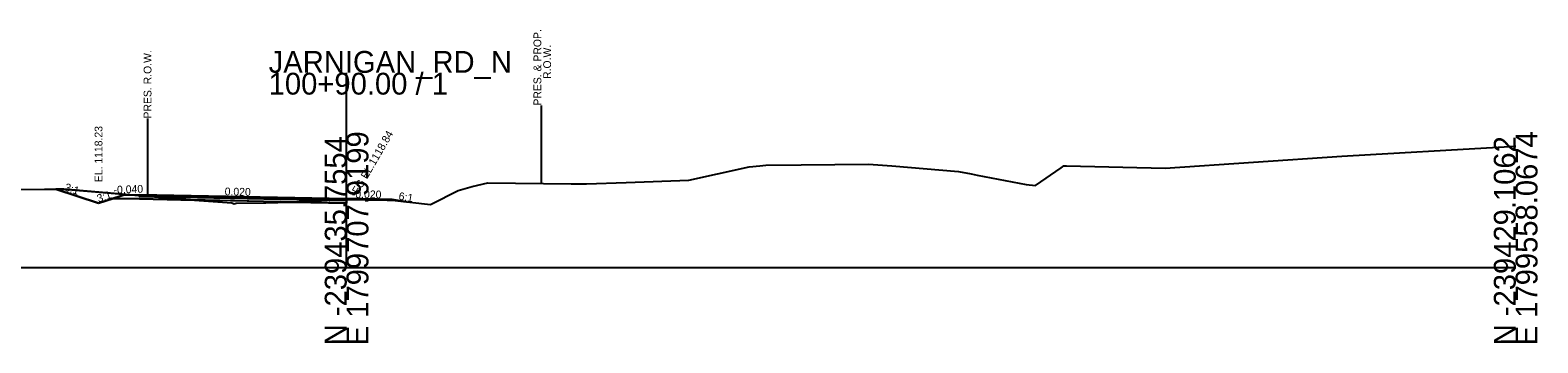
# Model space of a CAD drawing. Extents: x 214513 to 217151, y 214739 to 216780.
# Drawn here: x 214857.8 to 215051.2, y 216738.7 to 216778.8 of the extents above; entities that cross this region are included whole.
import ezdxf

# ---------------------------------------------------------------- set-up
doc = ezdxf.new("R2010")
doc.units = 0
for name, color, linetype in [('CONCEPT - TRANSPORTATION - Roads Text', 7, 'Continuous'), ('DESIGN - CENTERLINE - Proposed', 7, 'Continuous'), ('DESIGN - CENTERLINE - Proposed Text', 7, 'Continuous'), ('DESIGN - DRAINAGE - Special Ditches', 7, 'Continuous'), ('DESIGN - EARTHWORK - Shapes', 7, 'Continuous'), ('DESIGN - TRANSPORTATION - Text', 7, 'Continuous'), ('DESIGN - TYPICAL - Slope Tie Text', 7, 'Continuous'), ('SURVEY - DTM GRAPHICS - Triangles', 7, 'Continuous'), ('SURVEY - PROPERTY - ROW Lines', 7, 'Continuous'), ('XSCell', 7, 'Continuous')]:
    doc.layers.add(name, color=color, linetype=linetype)

msp = doc.modelspace()

# ---------------------------------------------------------------- linework, layer by layer
at = {"layer": 'DESIGN - DRAINAGE - Special Ditches'}
for points in [[(214866.53, 216756.6), (214861.04, 216758.43)], [(214869.7, 216757.65), (214866.53, 216756.6)], [(214871.78, 216757.74), (214871.78, 216757.49), (214877.07, 216757.38), (214898.36, 216756.95), (214898.36, 216756.62), (214877.07, 216757.05), (214871.78, 216757.16), (214868.41, 216757.22), (214869.7, 216757.65), (214871.78, 216757.74)], [(214871.78, 216757.74), (214898.36, 216757.2), (214898.36, 216757.1), (214898.36, 216757.1), (214871.78, 216757.64), (214871.78, 216757.64), (214871.78, 216757.64), (214871.78, 216757.74), (214871.78, 216757.74)], [(214871.78, 216757.64), (214898.36, 216757.1), (214898.36, 216756.95), (214898.36, 216756.95), (214871.78, 216757.49), (214871.78, 216757.49), (214871.78, 216757.49), (214871.78, 216757.64), (214871.78, 216757.64)], [(214904.19, 216757.09), (214898.36, 216757.2), (214898.36, 216757.1), (214898.36, 216757.1), (214904.19, 216756.99), (214904.19, 216756.99), (214904.19, 216756.99), (214904.19, 216757.09), (214904.19, 216757.09)], [(214904.19, 216757.09), (214906.05, 216756.78)]]:
    msp.add_lwpolyline(points, dxfattribs=at)
at = {"layer": 'DESIGN - EARTHWORK - Shapes'}
for p, q in [((214861.04, 216758.43), (214866.53, 216756.6)), ((214869.7, 216757.65), (214868.41, 216757.22)), ((214869.7, 216757.65), (214870.53, 216757.69)), ((214870.53, 216757.69), (214869.7, 216757.65)), ((214871.78, 216757.58), (214870.53, 216757.69)), ((214871.78, 216757.58), (214871.78, 216757.49)), ((214871.78, 216757.49), (214873.22, 216757.46)), ((214891.44, 216756.76), (214878.32, 216757.03)), ((214891.44, 216756.76), (214898.36, 216756.62)), ((214898.36, 216756.95), (214896.14, 216757)), ((214896.14, 216757), (214898.36, 216756.95)), ((214898.36, 216757.13), (214898.12, 216757.11)), ((214898.12, 216757.11), (214898.36, 216757.1)), ((214898.36, 216757.1), (214898.36, 216757.13)), ((214898.36, 216757.13), (214898.36, 216757.1)), ((214898.36, 216757.1), (214903.57, 216757)), ((214898.36, 216756.62), (214898.36, 216756.95)), ((214906.05, 216756.78), (214904.19, 216757.09))]:
    msp.add_line(p, q, dxfattribs=at)
for points in [[(214870.53, 216757.69), (214862.09, 216758.4), (214861.1, 216758.43), (214861.04, 216758.43)], [(214866.53, 216756.6), (214868.41, 216757.22), (214869.7, 216757.65)], [(214868.41, 216757.22), (214871.78, 216757.16), (214877.07, 216757.05), (214878.32, 216757.03)], [(214873.22, 216757.46), (214871.78, 216757.49), (214871.78, 216757.58)], [(214873.22, 216757.46), (214872.82, 216757.49), (214871.78, 216757.58)], [(214878.32, 216757.03), (214878.26, 216757.03), (214873.22, 216757.46)], [(214878.32, 216757.03), (214883.63, 216756.66), (214883.94, 216756.54), (214884.19, 216756.6), (214888.01, 216756.64), (214889.53, 216756.71), (214891.44, 216756.76)], [(214896.14, 216757), (214892.27, 216756.79), (214891.44, 216756.76)], [(214898.12, 216757.11), (214898.05, 216757.11), (214896.14, 216757)], [(214898.36, 216756.95), (214898.36, 216757.1), (214898.12, 216757.11)], [(214903.57, 216757), (214899.2, 216757.13), (214898.68, 216757.15), (214898.36, 216757.13)], [(214904.19, 216757.09), (214904.19, 216756.99), (214903.57, 216757)], [(214903.57, 216757), (214904.19, 216756.98), (214906.05, 216756.78)]]:
    msp.add_lwpolyline(points, dxfattribs=at)
at = {"layer": 'SURVEY - DTM GRAPHICS - Triangles'}
msp.add_lwpolyline([(214847.06, 216758.36), (214859.61, 216758.4), (214861.1, 216758.43), (214862.09, 216758.4), (214878.26, 216757.03), (214883.63, 216756.66), (214883.94, 216756.54), (214884.19, 216756.6), (214888.01, 216756.64), (214889.53, 216756.71), (214892.27, 216756.79), (214898.05, 216757.11), (214898.68, 216757.15), (214899.2, 216757.13), (214904.19, 216756.98), (214909.11, 216756.44), (214909.16, 216756.44), (214909.22, 216756.47), (214912.69, 216758.25), (214914.46, 216758.74), (214916.49, 216759.22), (214927.17, 216759.11), (214929.14, 216759.08), (214934.21, 216759.27), (214942.28, 216759.55), (214945.97, 216760.37), (214950.03, 216761.28), (214951.39, 216761.43), (214952.16, 216761.51), (214956.69, 216761.55), (214965.34, 216761.64), (214968.31, 216761.39), (214976.85, 216760.67), (214978.5, 216760.37), (214979.27, 216760.21), (214985.54, 216759.03), (214986.73, 216758.88), (214990.05, 216761.16), (214990.4, 216761.41), (214990.71, 216761.4), (215003.38, 216761.09), (215026.06, 216762.65), (215029.72, 216762.88), (215043.12, 216763.65), (215048.36, 216763.95)], dxfattribs=at)
at = {"layer": 'SURVEY - PROPERTY - ROW Lines'}
for points in [[(214923.34, 216769.15), (214923.34, 216759.15)], [(214872.82, 216767.49), (214872.82, 216757.49)]]:
    msp.add_lwpolyline(points, dxfattribs=at)
at = {"layer": 'XSCell'}
for p, q in [((214898.36, 216748.36), (214898.36, 216773.36)), ((214748.36, 216748.36), (214898.36, 216748.36)), ((214898.36, 216748.36), (215048.36, 216748.36))]:
    msp.add_line(p, q, dxfattribs=at)

# ---------------------------------------------------------------- texts
at = {"layer": 'CONCEPT - TRANSPORTATION - Roads Text'}
for s, rotation, p in [('-0.040', 2.2906, (214868.48, 216757.82)), ('0.020', 358.8542, (214882.71, 216757.62)), ('-0.020', 358.8542, (214899.03, 216757.3))]:
    msp.add_text(s, height=1, rotation=rotation, dxfattribs=at).set_placement(p)
at = {"layer": 'DESIGN - CENTERLINE - Proposed'}
msp.add_text('EL. 1118.23', height=1, rotation=90, dxfattribs=at).set_placement((214867.03, 216759.31))
at = {"layer": 'DESIGN - CENTERLINE - Proposed Text'}
msp.add_text('FG EL.1118.84', height=1, rotation=60, dxfattribs=at).set_placement((214899.86, 216757.7))
at = {"layer": 'DESIGN - TRANSPORTATION - Text'}
for s, p in [('PRES. & PROP. ', (214923.34, 216769.15)), ('R.O.W.', (214924.59, 216772.57)), ('PRES. R.O.W.', (214873.32, 216767.49))]:
    msp.add_text(s, height=1, rotation=90, dxfattribs=at).set_placement(p)
at = {"layer": 'DESIGN - TYPICAL - Slope Tie Text'}
for s, rotation, p in [('3:1', 341.5651, (214862.09, 216758.26)), ('3:1', 18.4349, (214866.52, 216756.7)), ('6:1', 350.5377, (214904.98, 216757.06))]:
    msp.add_text(s, height=1, rotation=rotation, dxfattribs=at).set_placement(p)
at = {"layer": 'XSCell'}
for s, p in [('JARNIGAN_RD_N', (214888.36, 216773.36)), ('100+90.00 / 1', (214888.36, 216770.56))]:
    msp.add_text(s, height=2.8, dxfattribs=at).set_placement(p)
for s, p in [('N -239435.7554', (214898.36, 216738.36)), ('E 1799707.9199', (214901.16, 216738.36)), ('N -239429.1062', (215048.36, 216738.36)), ('E 1799558.0674', (215051.16, 216738.36))]:
    msp.add_text(s, height=2.8, rotation=90, dxfattribs=at).set_placement(p)

doc.saveas('drawing.dxf')
